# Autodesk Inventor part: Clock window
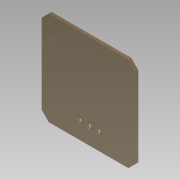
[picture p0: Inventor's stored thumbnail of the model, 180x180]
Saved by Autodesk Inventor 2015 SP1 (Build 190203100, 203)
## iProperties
Created: 2015-05
Part Number: Clock window
Material: Polycarbonate, Clear
Document SubType Name: Modeling
Designer: kazys
Density: 1.2 g/cm^3
Appearance: Clear - Yellow
Author: kazys
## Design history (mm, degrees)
sketch "Sketch1"
  geometry: L1 (-41.275, 41.275)-(41.275, 41.275); L2 (41.275, 41.275)-(41.275, -41.275); L3 (41.275, -41.275)-(-41.275, -41.275); L4 (-41.275, -41.275)-(-41.275, 41.275); 3 further points
  constraints: 8 end point, 2 midpoint, 2 parallel, 1 horizontal, 1 horizontal alignment, 1 perpendicular, 1 vertical alignment
  dimensions: "d0" = 82.55 distance of L2.end L3.end; "d1" = 82.55 distance of L1.end L2.end
extrude "Extrusion1" new body sketch "Sketch1" distance "d2" = 2.5; taper "d3" = 0 deg
chamfer "Chamfer1" distance "d5" = 6.35; stored, may be unused: second distance "d6" = 3.175, angle "d7" = 45 deg
sketch "Sketch3"
  geometry: C1 r 2.115 at (8.08, -27.099) reference; C2 r 2.115 at (-0.175, -27.099) reference; C3 r 2.115 at (-8.43, -27.099) reference; C4 r 2.286 at (8.08, -27.099); C5 r 2.286 at (-0.175, -27.099); C6 r 2.286 at (-8.43, -27.099); 1 further point
  constraints: 3 centre point, 3 coincident
  dimensions: "d8" = 4.572 diameter of C4; "d9" = 4.572 diameter of C5; "d10" = 4.572 diameter of C6
extrude "Extrusion2" cut sketch "Sketch3" stored distance "d11" = 25.4; taper "d12" = 0 deg
body "Solid1"
node "Reference2"
node "Reference3"
node "Reference4"
